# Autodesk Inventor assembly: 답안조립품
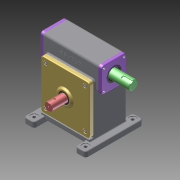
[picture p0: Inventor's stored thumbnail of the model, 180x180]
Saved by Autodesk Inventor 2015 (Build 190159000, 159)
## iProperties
Created: 2025-06
Part Number: 답안조립품
Document SubType Name: Assembly
Designer: User
Author: User
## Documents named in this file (13)
- C:\Users\User\Downloads\750603V1008\답안조립품.iam
- C:\Users\User\Downloads\750603V1008\가져온 구성요소\6각 구멍붙이 볼트 M8x20\6각 구멍붙이 볼트 M8x20.ipt
- C:\Users\User\Downloads\750603V1008\가져온 구성요소\깊은 홈 볼 베어링 6206\깊은 홈 볼 베어링 6206.ipt
- C:\Users\User\Downloads\750603V1008\가져온 구성요소\깊은 홈 볼 베어링 6209\깊은 홈 볼 베어링 6209.ipt
- C:\Users\User\Downloads\750603V1008\가져온 구성요소\뒷커버\뒷커버.ipt
- C:\Users\User\Downloads\750603V1008\본체.ipt
- C:\Users\User\Downloads\750603V1008\가져온 구성요소\앞커버\앞커버.ipt
- C:\Users\User\Downloads\750603V1008\가져온 구성요소\오일 실 30 42 7\오일 실 30 42 7.ipt
- C:\Users\User\Downloads\750603V1008\가져온 구성요소\오일 실 35 55 11\오일 실 35 55 11.ipt
- C:\Users\User\Downloads\750603V1008\가져온 구성요소\웜 샤프트\웜 샤프트.ipt
- C:\Users\User\Downloads\750603V1008\가져온 구성요소\웜 휠 커버\웜 휠 커버.ipt
- C:\Users\User\Downloads\750603V1008\가져온 구성요소\웜 휠\웜 휠.ipt
- C:\Users\User\Downloads\750603V1008\가져온 구성요소\6각 구멍붙이 볼트 M6x12\6각 구멍붙이 볼트 M6x12.ipt
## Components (12 placed, 2 different names)
1. 6각 구멍붙이 볼트 M8x20:1
2. 6각 구멍붙이 볼트 M8x20:2
3. 6각 구멍붙이 볼트 M8x20:3
4. 6각 구멍붙이 볼트 M8x20:4
5. 6각 구멍붙이 볼트 M6x12:1
6. 6각 구멍붙이 볼트 M6x12:2
7. 6각 구멍붙이 볼트 M6x12:3
8. 6각 구멍붙이 볼트 M6x12:4
9. 6각 구멍붙이 볼트 M6x12:5
10. 6각 구멍붙이 볼트 M6x12:6
11. 6각 구멍붙이 볼트 M6x12:7
12. 6각 구멍붙이 볼트 M6x12:8
